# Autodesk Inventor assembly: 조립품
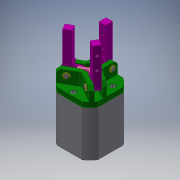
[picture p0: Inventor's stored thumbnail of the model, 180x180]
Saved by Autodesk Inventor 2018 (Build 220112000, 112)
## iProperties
Created: 2020-02
Part Number: 조립품
Document SubType Name: Assembly
Designer: Administrator
Author: Administrator
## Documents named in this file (13)
- C:\Users\Administrator\Desktop\700206V1024\조립품.iam
- C:\Users\Administrator\Desktop\700206V1024\본체.ipt
- C:\Users\Administrator\Desktop\700206V1024\피스톤.ipt
- C:\Users\Administrator\Desktop\700206V1024\O-RING 34x40.ipt
- C:\Users\Administrator\Desktop\700206V1024\O-RING 12x16.ipt
- C:\Users\Administrator\Desktop\700206V1024\로드.ipt
- C:\Users\Administrator\Desktop\700206V1024\본체헤드.ipt
- C:\Users\Administrator\Desktop\700206V1024\핑거.ipt
- C:\Users\Administrator\Desktop\700206V1024\E링.ipt
- C:\Users\Administrator\Desktop\700206V1024\핀 A.ipt
- C:\Users\Administrator\Desktop\700206V1024\핀 B.ipt
- C:\Users\Administrator\Desktop\700206V1024\O-RING 18x22.ipt
- C:\Users\Administrator\Desktop\700206V1024\볼트 M4.ipt
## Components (20 placed, 8 different names)
1. 피스톤:1
2. O-RING 34x40:1
3. O-RING 12x16:1
4. 핑거:1
5. O-RING 18x22:1
6. O-RING 34x40:2
7. E링:1
8. 핀 A:1
9. 핀 B:1
10. E링:2
11. 핑거:2
12. 핑거:3
13. E링:3
14. E링:4
15. E링:5
16. E링:6
17. 핀 B:2
18. 핀 B:3
19. 핀 A:2
20. 핀 A:3
